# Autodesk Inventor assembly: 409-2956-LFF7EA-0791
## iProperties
Created: 2010-09
Part Number: 409-2956-LFF7EA-0791
Document SubType Name: Weldment
Designer: S. Boerckel
Weld Material: Welded Aluminum-6061
Mass: 6030.48 g
Surface Area: 2434.61 cm^2
Volume: 768.052 cm^3
Density: 7.85166 g/cm^3
Description: DISCHARGE PIPE STAND
User Status: WELD
Material: WELDMENT
SMR: =<MATERIAL>
Author: S. Boerckel
Revision Number: A
